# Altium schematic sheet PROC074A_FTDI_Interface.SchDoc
size 431 x 279 mm; Date: Not shown in title block; ApprovedBy: Not shown in title block; CheckedBy: Not shown in title block; Author: Not shown in title block; CompanyName: Not shown in title block; Engineer: Not shown in title block; Organization: Not shown in title block; Address1: Not shown in title block; Address2: Not shown in title block; Address3: Not shown in title block; Address4: Not shown in title block; DocumentNumber: 1; Revision: Use project parameter SCH_Rev; SheetNumber: 16; SheetTotal: 22; PageSetup: Record=PageOptions¦CenterHorizontal=True¦CenterVertical=True¦PrintScale=1.00¦XCorrection=1.00¦YCorrection=1.00¦PrintKind=0¦BorderSize=5000000¦LeftOffset=0¦BottomOffset=0¦Orientation=2¦PaperLength=1000¦PaperWidth=1000¦Scale=100¦PaperSource=15¦PrintQuality=600¦MediaType=1¦DitherType=10¦PaperKind=Letter¦PrintScaleMode=1
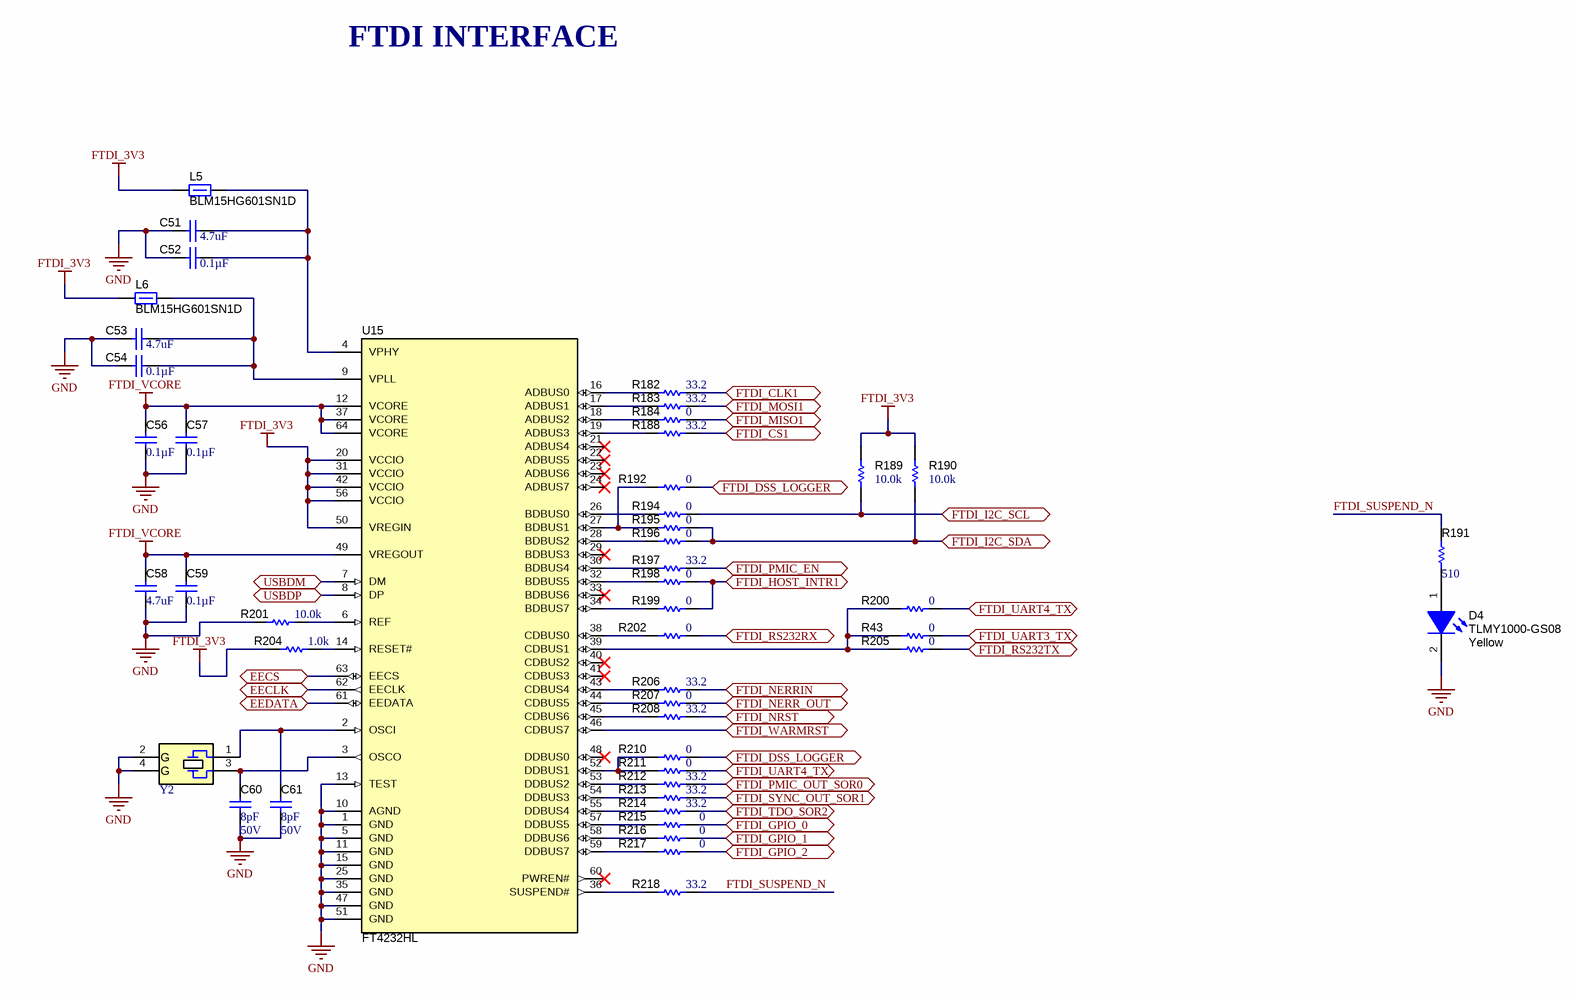
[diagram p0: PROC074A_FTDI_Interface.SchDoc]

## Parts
C51  ValueDisplayed: 4.7uF  [0603]  (hidden comment: C1608X7S1A475K080AC)
C52  ValueDisplayed: 0.1µF  [0402]  (hidden comment: C0402C104K8RACTU)
C53  ValueDisplayed: 4.7uF  [0603]  (hidden comment: C1608X7S1A475K080AC)
C54  ValueDisplayed: 0.1µF  [0402]  (hidden comment: C0402C104K8RACTU)
C56  ValueDisplayed: 0.1µF  [0402]  (hidden comment: C0402C104K8RACTU)
C57  ValueDisplayed: 0.1µF  [0402]  (hidden comment: C0402C104K8RACTU)
C58  ValueDisplayed: 4.7uF  [0603]  (hidden comment: C1608X7S1A475K080AC)
C59  ValueDisplayed: 0.1µF  [0402]  (hidden comment: C0402C104K8RACTU)
C60  VDC_V: 50V  ValueDisplayed: 8pF  [0402]  (hidden comment: GRM1555C1H8R0DA01D)
C61  VDC_V: 50V  ValueDisplayed: 8pF  [0402]  (hidden comment: GRM1555C1H8R0DA01D)
D4  TLMY1000-GS08  value Yellow  [TLMx1000_Yellow]
L5  BLM15HG601SN1D  [0402]
L6  BLM15HG601SN1D  [0402]
R43  ValueDisplayed: 0  [0402]  (hidden comment: ERJ-2GE0R00X)
R182  ValueDisplayed: 33.2  [0402]  (hidden comment: CRCW040233R2FKED)
R183  ValueDisplayed: 33.2  [0402]  (hidden comment: CRCW040233R2FKED)
R184  ValueDisplayed: 0  [0402]  (hidden comment: ERJ-2GE0R00X)
R188  ValueDisplayed: 33.2  [0402]  (hidden comment: CRCW040233R2FKED)
R189  ValueDisplayed: 10.0k  [0402]  (hidden comment: CRCW040210K0FKED)
R190  ValueDisplayed: 10.0k  [0402]  (hidden comment: CRCW040210K0FKED)
R191  ValueDisplayed: 510  [0402]  (hidden comment: ERJ-2GEJ511X)
R192  ValueDisplayed: 0  [0402]  (hidden comment: ERJ-2GE0R00X)
R194  ValueDisplayed: 0  [0402]  (hidden comment: ERJ-2GE0R00X)
R195  ValueDisplayed: 0  [0402]  (hidden comment: ERJ-2GE0R00X)
R196  ValueDisplayed: 0  [0402]  (hidden comment: ERJ-2GE0R00X)
R197  ValueDisplayed: 33.2  [0402]  (hidden comment: CRCW040233R2FKED)
R198  ValueDisplayed: 0  [0402]  (hidden comment: ERJ-2GE0R00X)
R199  ValueDisplayed: 0  [0402]  (hidden comment: ERJ-2GE0R00X)
R200  ValueDisplayed: 0  [0402]  (hidden comment: ERJ-2GE0R00X)
R201  ValueDisplayed: 10.0k  [0402]  (hidden comment: CRCW040210K0FKED)
R202  ValueDisplayed: 0  [0402]  (hidden comment: ERJ-2GE0R00X)
R204  ValueDisplayed: 1.0k  [0402]  (hidden comment: ERJ-2GEJ102X)
R205  ValueDisplayed: 0  [0402]  (hidden comment: ERJ-2GE0R00X)
R206  ValueDisplayed: 33.2  [0402]  (hidden comment: CRCW040233R2FKED)
R207  ValueDisplayed: 0  [0402]  (hidden comment: ERJ-2GE0R00X)
R208  ValueDisplayed: 33.2  [0402]  (hidden comment: CRCW040233R2FKED)
R210  ValueDisplayed: 0  [0402]  (hidden comment: ERJ-2GE0R00X)
R211  ValueDisplayed: 0  [0402]  (hidden comment: ERJ-2GE0R00X)
R212  ValueDisplayed: 33.2  [0402]  (hidden comment: CRCW040233R2FKED)
R213  ValueDisplayed: 33.2  [0402]  (hidden comment: CRCW040233R2FKED)
R214  ValueDisplayed: 33.2  [0402]  (hidden comment: CRCW040233R2FKED)
R215  ValueDisplayed: 0  [0402]  (hidden comment: ERJ-2GE0R00X)
R216  ValueDisplayed: 0  [0402]  (hidden comment: ERJ-2GE0R00X)
R217  ValueDisplayed: 0  [0402]  (hidden comment: ERJ-2GE0R00X)
R218  ValueDisplayed: 33.2  [0402]  (hidden comment: CRCW040233R2FKED)
U15  FT4232HL  [LQFP64_N]
Y2  NX3225SA-12.000M-STD-CRS-2  [NDK_NX3225SA]  (value not drawn)

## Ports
EECLK, EECS, EEDATA, FTDI_CLK1, FTDI_CS1, FTDI_DSS_LOGGER, FTDI_GPIO_0, FTDI_GPIO_1, FTDI_GPIO_2, FTDI_HOST_INTR1, FTDI_I2C_SCL, FTDI_I2C_SDA, FTDI_MISO1, FTDI_MOSI1, FTDI_NERR_OUT, FTDI_NERRIN, FTDI_NRST, FTDI_PMIC_EN, FTDI_PMIC_OUT_SOR0, FTDI_RS232RX, FTDI_RS232TX, FTDI_SYNC_OUT_SOR1, FTDI_TDO_SOR2, FTDI_UART3_TX, FTDI_UART4_TX, FTDI_WARMRST, USBDM, USBDP

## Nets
FTDI_3V3: L5.1 L6.1 R189.2 R190.2 R204.1 U15.20(VCCIO) U15.31(VCCIO) U15.42(VCCIO) U15.50(VREGIN) U15.56(VCCIO)
FTDI_VCORE: C56.1 C57.1 C58.1 C59.1 U15.12(VCORE) U15.37(VCORE) U15.49(VREGOUT) U15.64(VCORE)
GND: C51.2 C52.1 C53.2 C54.1 C56.2 C57.2 C58.2 C59.2 C60.2 C61.2 D4.2(K) R201.1 U15.1(GND) U15.5(GND) U15.10(AGND) U15.11(GND) U15.13(TEST) U15.15(GND) U15.25(GND) U15.35(GND) U15.47(GND) U15.51(GND) Y2.2(GND) Y2.4(GND)
EECLK: U15.62(EECLK) ; port EECLK
EECS: U15.63(EECS) ; port EECS
EEDATA: U15.61(EEDATA) ; port EEDATA
FTDI_CLK1: R182.2 ; port FTDI_CLK1
FTDI_CS1: R188.2 ; port FTDI_CS1
FTDI_DSS_LOGGER: R192.2 R210.2 ; port FTDI_DSS_LOGGER
FTDI_GPIO_0: R215.2 ; port FTDI_GPIO_0
FTDI_GPIO_1: R216.2 ; port FTDI_GPIO_1
FTDI_GPIO_2: R217.2 ; port FTDI_GPIO_2
FTDI_HOST_INTR1: R198.2 R199.2 ; port FTDI_HOST_INTR1
FTDI_I2C_SCL: R189.1 R194.2 ; port FTDI_I2C_SCL
FTDI_I2C_SDA: R190.1 R195.2 R196.2 ; port FTDI_I2C_SDA
FTDI_MISO1: R184.2 ; port FTDI_MISO1
FTDI_MOSI1: R183.2 ; port FTDI_MOSI1
FTDI_NERR_OUT: R207.2 ; port FTDI_NERR_OUT
FTDI_NERRIN: R206.2 ; port FTDI_NERRIN
FTDI_NRST: R208.2 ; port FTDI_NRST
FTDI_PMIC_EN: R197.2 ; port FTDI_PMIC_EN
FTDI_PMIC_OUT_SOR0: R212.2 ; port FTDI_PMIC_OUT_SOR0
FTDI_RS232RX: R202.2 ; port FTDI_RS232RX
FTDI_RS232TX: R205.2 ; port FTDI_RS232TX
FTDI_SUSPEND_N: R191.2 R218.2
FTDI_SYNC_OUT_SOR1: R213.2 ; port FTDI_SYNC_OUT_SOR1
FTDI_TDO_SOR2: R214.2 ; port FTDI_TDO_SOR2
FTDI_UART3_TX: R43.2 ; port FTDI_UART3_TX
FTDI_UART4_TX: R200.2 R211.2 ; port FTDI_UART4_TX
FTDI_WARMRST: U15.46(CDBUS7) ; port FTDI_WARMRST
USBDM: U15.7(DM) ; port USBDM
USBDP: U15.8(DP) ; port USBDP
NetC51_1: C51.1 C52.2 L5.2 U15.4(VPHY)
NetC53_1: C53.1 C54.2 L6.2 U15.9(VPLL)
NetC60_1: C60.1 U15.3(OSCO) Y2.3
NetC61_1: C61.1 U15.2(OSCI) Y2.1
NetD4_1: D4.1(A) R191.1
NetR43_1: R43.1 R200.1 R205.1 U15.39(CDBUS1)
NetR182_1: R182.1 U15.16(ADBUS0)
NetR183_1: R183.1 U15.17(ADBUS1)
NetR184_1: R184.1 U15.18(ADBUS2)
NetR188_1: R188.1 U15.19(ADBUS3)
NetR192_1: R192.1 R195.1 U15.27(BDBUS1)
NetR194_1: R194.1 U15.26(BDBUS0)
NetR196_1: R196.1 U15.28(BDBUS2)
NetR197_1: R197.1 U15.30(BDBUS4)
NetR198_1: R198.1 U15.32(BDBUS5)
NetR199_1: R199.1 U15.34(BDBUS7)
NetR201_2: R201.2 U15.6(REF)
NetR202_1: R202.1 U15.38(CDBUS0)
NetR204_2: R204.2 U15.14(RESET#)
NetR206_1: R206.1 U15.43(CDBUS4)
NetR207_1: R207.1 U15.44(CDBUS5)
NetR208_1: R208.1 U15.45(CDBUS6)
NetR210_1: R210.1 R211.1 U15.52(DDBUS1)
NetR212_1: R212.1 U15.53(DDBUS2)
NetR213_1: R213.1 U15.54(DDBUS3)
NetR214_1: R214.1 U15.55(DDBUS4)
NetR215_1: R215.1 U15.57(DDBUS5)
NetR216_1: R216.1 U15.58(DDBUS6)
NetR217_1: R217.1 U15.59(DDBUS7)
NetR218_1: R218.1 U15.36(SUSPEND#)

Not connected (* = marked no-connect by the designer): U15 21(ADBUS4)* 22(ADBUS5)* 23(ADBUS6)* 24(ADBUS7)* 29(BDBUS3)* 33(BDBUS6)* 40(CDBUS2)* 41(CDBUS3)* 48(DDBUS0)* 60(PWREN#)*

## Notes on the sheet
- FTDI INTERFACE

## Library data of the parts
C51 C53 C58 = CMP-0007058-4: CAP, CERM, 4.7 uF, 10 V, +/- 10%, X7S, 0603; Manufacturer: TDK; TaMin_C: -55°C; Polarized: N; SizeAreaWB_mm2: 4.68; Value1: Unknown; U/M: EA; Value: 4.7uF; TaMax_C: 125°C; SizeZ_mm: 1; SizeX_mm: 1.6; SizeY_mm: 0.8; Value2: 10V; SizeArea_mm2: 1.28; CompType: Capacitor; Cap_F: 4.7µF; AEC Category: Q200
C52 C54 C56 C57 C59 = CMP-0078241-1: CAP, CERM, 0.1 µF, 10 V,+/- 10%, X7R, 0402; Manufacturer: Kemet; TaMin_C: -55°C; Polarized: N; SizeAreaWB_mm2: 3; U/M: EA; Value: 0.1uF; TaMax_C: 125°C; SizeZ_mm: 0.6; SizeX_mm: 1; SizeY_mm: 0.5; Value2: 10V; CompType: Capacitor; Cap_F: 100nF; AEC Category: Q200
C60 C61 = CMP-0006494-2: CAP, CERM, 8 pF, 50 V, +/- 6%, C0G/NP0, 0402; Manufacturer: MuRata; TaMin_C: -55°C; Polarized: N; SizeAreaWB_mm2: 3; Value1: Unknown; U/M: EA; Value: 8pF; TaMax_C: 125°C; SizeZ_mm: 0.6; SizeX_mm: 1; SizeY_mm: 0.5; AEC Category: Q200
D4 = CMP-0078196-1: LED, Yellow, SMD; Manufacturer: Vishay-Semiconductor; Tjmax_C: 120°C; SizeAreaWB_mm2: 4.68; Vr_V: 6V; Power_TotalModule: 40mW; Angle: 160; SizeArea_mm2: 1.28; Ir_A: 10µA; SizeZ_mm: 0.65; Io_A: 2mA; Vf_V: 1.8V; SizeY_mm: 0.8; U/M: EA; Value1: .04W; SizeX_mm: 1.6; Type: AlInGaP
L5 L6 = CMP-0081523-1: Ferrite Bead, 600 ohm @ 100 MHz, 0.3 A, 0402; Manufacturer: MuRata; SizeAreaWB_mm2: 3; SizeArea_mm2: 0.5; Value: 600 ohm; SizeZ_mm: 0.6; Imax_A: 3dA; ZTyp@100MHz_Ohm: 600; Value2: 0.3A; Value1: 0.7 ohm; DCR_ohm: 7d; SizeX_mm: 1; Ztyp@1GHz_Ohm: 1k
R43 R192 R202 R205 R211 R215-R217 = CMP-0026992-3: RES, 0, 5%, 0.1 W, AEC-Q200 Grade 0, 0402; Manufacturer: Panasonic; Power_W: 100mW; TempCo: 600 ppm/C; Value_Code: 0000; Value: 0; EIA_Code: E24; SizeX_mm: 1; SizeY_mm: 0.5; SizeZ_mm: 0.6; Value2: 0.1W; CompType: Resistor; AEC Qualified: Y; VDC_V: 50V; AEC Category: Q200; SizeAreaWB_mm2: 3; INSTALLATION: DNP
R182 R183 R188 R197 R206 R208 R212-R214 R218 = CMP-0026299-2: RES, 33.2, 1%, 0.063 W, AEC-Q200 Grade 0, 0402; Manufacturer: Vishay-Dale; Power_W: 63mW; TempCo: 100 ppm/C; Value_Code: 33R2; Value: 33.2; EIA_Code: E96; SizeX_mm: 1; SizeY_mm: 0.5; SizeZ_mm: 0.6; Value2: 0.063W; AEC Qualified: Y; VDC_V: 50V; AEC Category: Q200; AEC Grade: 0
R184 R194-R196 R198-R200 R207 R210 = CMP-0026992-3: RES, 0, 5%, 0.1 W, AEC-Q200 Grade 0, 0402; Manufacturer: Panasonic; Power_W: 100mW; TempCo: 600 ppm/C; Value_Code: 0000; Value: 0; EIA_Code: E24; SizeX_mm: 1; SizeY_mm: 0.5; SizeZ_mm: 0.6; Value2: 0.1W; AEC Qualified: Y; VDC_V: 50V; AEC Category: Q200; SizeAreaWB_mm2: 3
R189 R190 = CMP-0025958-3: RES, 10.0 k, 1%, 0.063 W, AEC-Q200 Grade 0, 0402; Manufacturer: Vishay-Dale; Power_W: 63mW; TempCo: 100 ppm/C; Value_Code: 10k0; Value: 10.0k; EIA_Code: E96; Res_ohm: 10k; SizeX_mm: 1; SizeY_mm: 0.5; SizeZ_mm: 0.6; Value2: 0.063W; CompType: Resistor; AEC Qualified: Y; VDC_V: 50V; AEC Category: Q200; AEC Grade: 0; INSTALLATION: DNP
R191 = CMP-0078212-1: RES, 510, 5%, 0.1 W, AEC-Q200 Grade 0, 0402; Manufacturer: Panasonic; Value_Code: 510R; SizeArea_mm2: 0.5; AEC Qualified: Y; AEC Category: Q200; Value: 510; SizeZ_mm: 0.6; EIA_Code: E24; TempCo: 200 ppm/C; AEC Grade: 0; Power_W: 100mW; VDC_V: 50V; Value2: 0.1W; U/M: EA; SizeX_mm: 1
R201 = CMP-0025958-3: RES, 10.0 k, 1%, 0.063 W, AEC-Q200 Grade 0, 0402; Manufacturer: Vishay-Dale; Power_W: 63mW; TempCo: 100 ppm/C; Value_Code: 10k0; Value: 10.0k; EIA_Code: E96; Res_ohm: 10k; SizeX_mm: 1; SizeY_mm: 0.5; SizeZ_mm: 0.6; Value2: 0.063W; AEC Qualified: Y; VDC_V: 50V; AEC Category: Q200; AEC Grade: 0
R204 = CMP-0078193-1: RES, 1.0 k, 5%, 0.1 W, AEC-Q200 Grade 0, 0402; Manufacturer: Panasonic; Value_Code: 1k00; SizeArea_mm2: 0.5; AEC Qualified: Y; AEC Category: Q200; Res_ohm: 1k; Value: 1.0k; SizeZ_mm: 0.6; Green_REACh: Passed; EIA_Code: E24; TempCo: 200 ppm/C; AEC Grade: 0; Power_W: 100mW; VDC_V: 50V; Value2: 0.1W; Green_Lifecycle: Active; U/M: EA; SizeX_mm: 1
U15 = CMP-0004747-1: Quad High Speed USB to Multipurpose UART/MPSSE IC; Manufacturer: FTDI
Y2 = CMP-0081529-1: Crystal, 12 MHz, 15 ppm, 8 pF, AEC-Q200 Grade 1, SMD; Manufacturer: NDK; TaMin_C: -40°C; Frequency Tolerance: 15 ppm; Frequency Stability: 50 ppm; Load Capacitance: 8 pF; Frequency_Fixed: 12MHz; TaMax_C: 125°C; AEC Qualified: Y; AEC Grade: 1; AEC Category: Q200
